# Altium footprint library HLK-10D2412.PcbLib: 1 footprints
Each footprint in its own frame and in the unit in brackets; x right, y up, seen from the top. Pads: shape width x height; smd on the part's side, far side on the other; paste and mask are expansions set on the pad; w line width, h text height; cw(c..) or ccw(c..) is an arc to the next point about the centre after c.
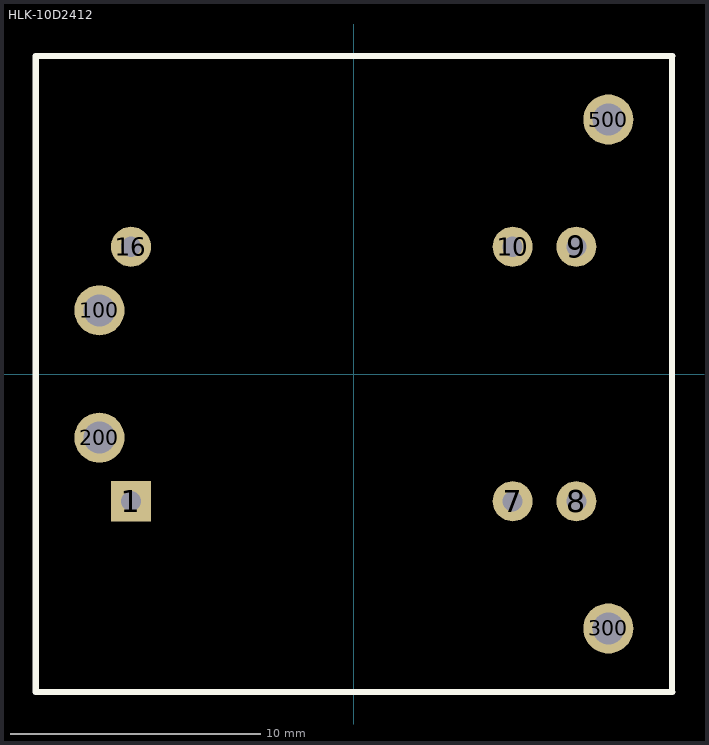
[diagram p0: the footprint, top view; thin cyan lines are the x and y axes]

## HLK-10D2412 [mm]
pads (10):
  rect 1.6x1.6 hole 0.8: 1(-8.9,-5.08)
  round 1.6 hole 0.8: 7(6.34,-5.08) 8(8.88,-5.08) 9(8.88,5.08) 10(6.34,5.08) 16(-8.9,5.08)
  round 2 hole 1.28: 100(-10.16,2.54) 200(-10.16,-2.54) 300(10.16,-10.16) 500(10.16,10.16)
Top Overlay:
  lines w0.25: 12.7,-12.7 12.7,12.7 ; 12.708,-12.7 -12.7,-12.7 -12.7,12.7 12.708,12.7
Mechanical 14:
  text "+Vout" at 8.636,3.556 h1.06
  text "-Vin" at -9.144,2.159 h1.06
  text "+Vin" at -8.89,-2.794 h1.06
  text "-Vout" at 6.985,9.779 h1.06
  text "+Vout" at 6.858,-10.414 h1.06
  text "-Vout" at 6.34,3.556 h1.06
  text "+Vin" at -7.747,4.826 h1.06
  text "-Vin" at -7.62,-5.334 h1.06
  text "NC" at 9.144,-3.937 h1.06
  text "NC" at 6.604,-3.937 h1.06
3D body "URB2405.STEP": height 11.7, standoff -4.1, extent -12.7,-12.573 12.7,12.827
